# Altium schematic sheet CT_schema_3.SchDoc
size 276 x 169 mm
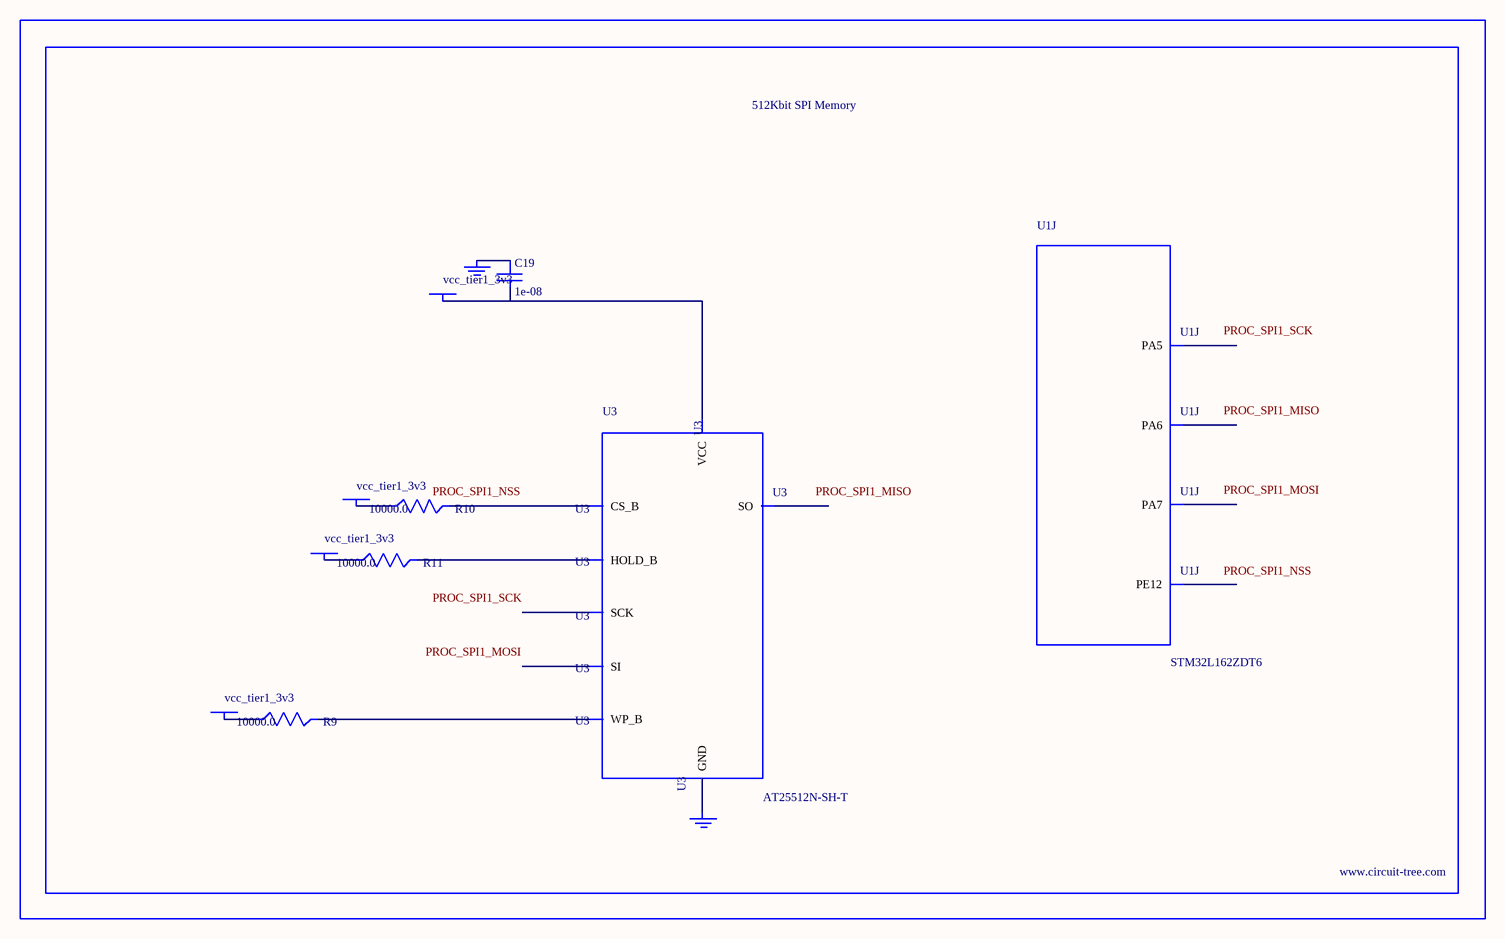
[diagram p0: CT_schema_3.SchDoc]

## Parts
BORDER2  (no value)
C19  1e-08  [C0402]
GND_INSTANCE_2_0  (no value)
GND_INSTANCE_2_1  (no value)
POWER_INSTANCE_2_0  vcc_tier1_3v3
POWER_INSTANCE_2_1  vcc_tier1_3v3
POWER_INSTANCE_2_2  vcc_tier1_3v3
POWER_INSTANCE_2_3  vcc_tier1_3v3
R9  10000.0  [R0603]
R10  10000.0  [R0603]
R11  10000.0  [R0603]
U1  STM32L162ZDT6  [LQFP144]  (part J of 11)
U3  AT25512N-SH-T  [SOIC-8]

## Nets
NetC19_1: C19.1 GND_INSTANCE_2_0.0(GND)
NetC19_2: C19.2 POWER_INSTANCE_2_3.0(PWR) U3.8(VCC)
NetGND_INSTANCE_2_1_0: GND_INSTANCE_2_1.0(GND) U3.4(GND)
NetPOWER_INSTANCE_2_0_0: POWER_INSTANCE_2_0.0(PWR) R10.1
NetPOWER_INSTANCE_2_1_0: POWER_INSTANCE_2_1.0(PWR) R9.1
NetPOWER_INSTANCE_2_2_0: POWER_INSTANCE_2_2.0(PWR) R11.1
NetR9_2: R9.2 U3.3(WP_B)
NetR10_2: R10.2 U3.1(CS_B)
NetR11_2: R11.2 U3.7(HOLD_B)

Not connected (* = marked no-connect by the designer): U1 41(PA5) 42(PA6) 43(PA7) 65(PE12); U3 2(SO) 5(SI) 6(SCK)

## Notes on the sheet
- Labels drawn without touching a wire or pin: PROC_SPI1_MISO, PROC_SPI1_MOSI, PROC_SPI1_NSS, PROC_SPI1_SCK

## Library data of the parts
BORDER2 = BORDER_PAGE2
C19 = C0402C103K3RAC
GND_INSTANCE_2_0 GND_INSTANCE_2_1 = GND
POWER_INSTANCE_2_0-POWER_INSTANCE_2_3 = PWR
R9-R11 = RC0603JR-0710KL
